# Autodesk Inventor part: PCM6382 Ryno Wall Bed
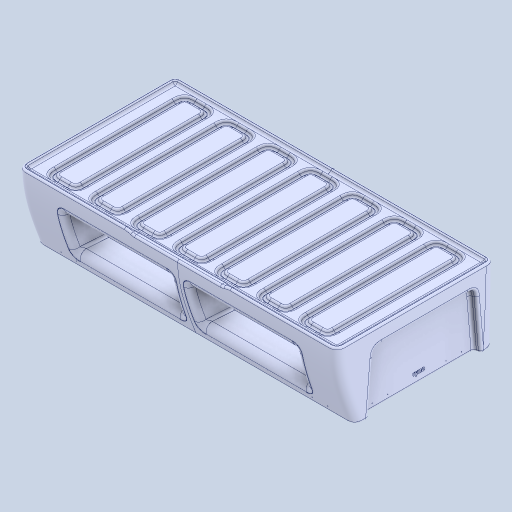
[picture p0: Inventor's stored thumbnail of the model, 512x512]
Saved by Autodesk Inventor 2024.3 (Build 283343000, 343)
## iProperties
Created: 2024-05
Part Number: PCM6382 Ryno Wall Bed
Material: Generic
Description: STEP AP214
Document SubType Name: Modeling
Designer: rohit.darbha
Density: 1 g/cm^3
Appearance: Default
Title: PCM6382 Ryno Wall Bed.STEP
Revision Number: ANY
Sending System: SolidWorks 2023
Preprocessor: SwSTEP 2.0
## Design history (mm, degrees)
combine "Combine3"
body "Solid1"
